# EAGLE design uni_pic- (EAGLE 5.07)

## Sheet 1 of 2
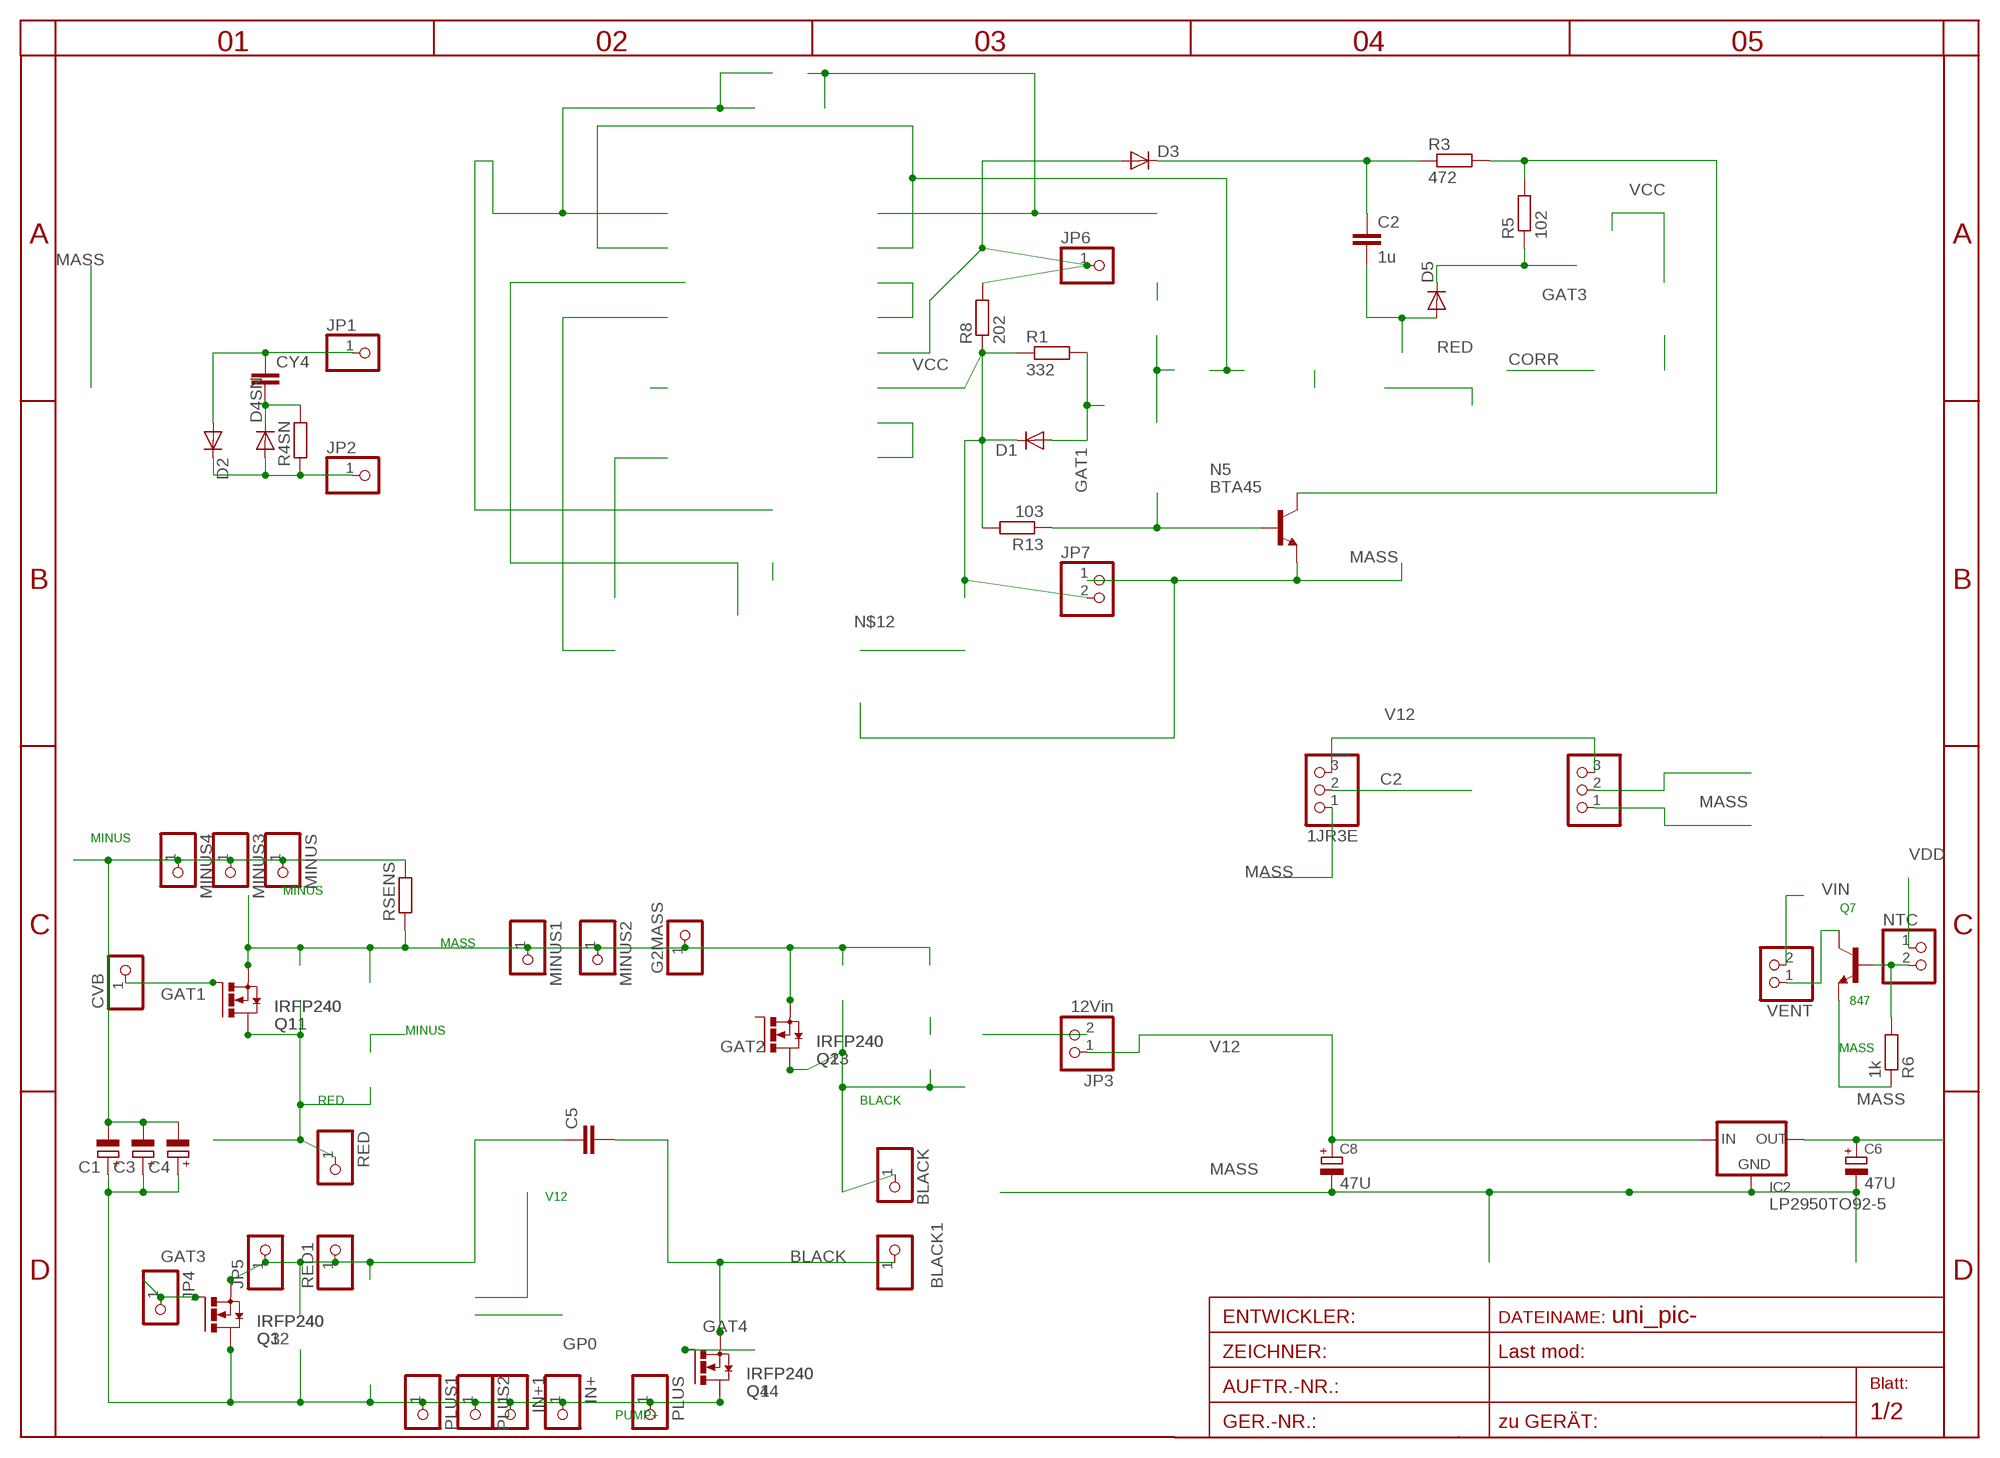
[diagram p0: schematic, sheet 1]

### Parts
1JR3E  PINHD-1X3  [1X03]
2JR4E3  PINHD-1X3  [1X03]
BLACK  PINHD-1X12MM3  [1X2MM3]
BLACK1  PINHD-1X12MM3  [1X2MM3]
C1  CPOL-EUE5-13  [E5-13]
C2  1u  C-EUC1206  [C1206]
C3  CPOL-EUE5-13  [E5-13]
C4  CPOL-EUE5-13  [E5-13]
C5  C-EU075-032X103  [C075-032X103]
C6  47U  CPOL-EUE5-6  [E5-6]
C8  47U  CPOL-EUE5-5  [E5-5]
CVB  PINHD-1X11MM0  [1X1MM0]
CY4  CXXC10B5  [XC10B5]
D1  DIODE-MINIMELF  [MINIMELF]
D2  DIODE-SMC  [SMC]
D3  DIODE-SMA-DO214  [SMA-DO214AC]
D4SN  DIODE-P1-10  [P1-10]
D5  DIODE-MINIMELF  [MINIMELF]
G2MASS  PINHD-1X11MM0  [1X1MM0]
IC2  LP2950TO92-5  [T092-5]
IN+  PINHD-1X12MM3  [1X2MM3]
IN+1  PINHD-1X12MM3  [1X2MM3]
JP1  PINHD-1X11MM0  [1X1MM0]
JP2  PINHD-1X11MM0  [1X1MM0]
JP3  12Vin  PINHD-1X2STR  [1X02]
JP4  PINHD-1X11MM0  [1X1MM0]
JP5  PINHD-1X11MM0  [1X1MM0]
JP6  PINHD-1X11X0.4  [1X01]
JP7  PINHD-1X2STR  [1X02]
MINUS  PINHD-1X12MM3  [1X2MM3]
MINUS1  PINHD-1X12MM3  [1X2MM3]
MINUS2  PINHD-1X12MM3  [1X2MM3]
MINUS3  PINHD-1X12MM3  [1X2MM3]
MINUS4  PINHD-1X12MM3  [1X2MM3]
N5  BTA45  SMBTA45HV  [SOT23HV]
NTC  PINHD-1X2STR  [1X02]
PLUS  PINHD-1X12MM3  [1X2MM3]
PLUS1  PINHD-1X12MM3  [1X2MM3]
PLUS2  PINHD-1X12MM3  [1X2MM3]
Q1  IRFP240  [TO247BV]
Q2  IRFP240  [TO247BV]
Q3  IRFP240  [TO247BV]
Q4  IRFP240  [TO247BV]
Q7  847  BC847ALT1SMD  [SOT23]
Q11  IRFP240  [TO247BV]
Q12  IRFP240  [TO247BV]
Q13  IRFP240  [TO247BV]
Q14  IRFP240  [TO247BV]
R1  332  R-EU_R0805  [R0805]
R3  472  R-EU_R0805  [R0805]
R4SN  R-EU_0207/10  [0207/10]
R5  102  R-EU_R1206  [R1206]
R6  1k  R-EU_R0805  [R0805]
R8  202  R-EU_R0805  [R0805]
R13  103  R-EU_0207/15  [0207/15]
RED  PINHD-1X12MM3  [1X2MM3]
RED1  PINHD-1X12MM3  [1X2MM3]
RSENS  R-EU_0204/7  [0204/7]
VENT  PINHD-1X2STR  [1X02]

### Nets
BLACK: BLACK1.1 BLACK.1 C5.2 Q2.D Q4.S Q13.D Q14.S
C1: 2JR4E3.2 ; also sheet 2
C2: 1JR3E.2 D1.C JP7.2 R1.1 R8.1 R13.2 ; also sheet 2
DRAIN: D2.C D4SN.A JP2.1 R4SN.1
GAT1: CVB.1 D1.A Q1.G Q11.G R1.2
GAT2: Q2.G Q13.G
GAT3: D5.C JP4.1 Q3.G Q12.G R5.1
GAT4: Q4.G Q14.G
MASS: 1JR3E.1 2JR4E3.1 C6.- C8.- G2MASS.1 IC2.2(GND) JP3.2 JP7.1 MINUS1.1 MINUS2.1 N5.2(E) Q1.S Q2.S Q7.2(E) Q11.S Q13.S R6.1 RSENS.1 ; also sheet 2
MINUS: C1.- C3.- C4.- MINUS3.1 MINUS4.1 MINUS.1 RSENS.2
N$4: C2.1 D3.K(C) R3.1
N$8: N5.3(C) R3.2 R5.2
N$9: NTC.2 Q7.1(B) R6.2
N$10: Q7.3(C) VENT.1
N$17: N5.1(B) R13.1
PUMP+: C1.+ C3.+ C4.+ IN+1.1 IN+.1 PLUS1.1 PLUS2.1 PLUS.1 Q3.D Q4.D Q12.D Q14.D ; also sheet 2
RED: C2.2 C5.1 D5.A JP5.1 Q1.D Q3.S Q11.D Q12.S RED1.1 RED.1
SNUB2: CY4.2 D4SN.C R4SN.2
SOURCE: CY4.1 D2.A JP1.1
V12: 1JR3E.3 2JR4E3.3 C8.+ IC2.3(IN) JP3.1
VCC: D3.A JP6.1 R8.2
VDD: C6.+ IC2.1(OUT) NTC.1 ; also sheet 2
VIN: VENT.2

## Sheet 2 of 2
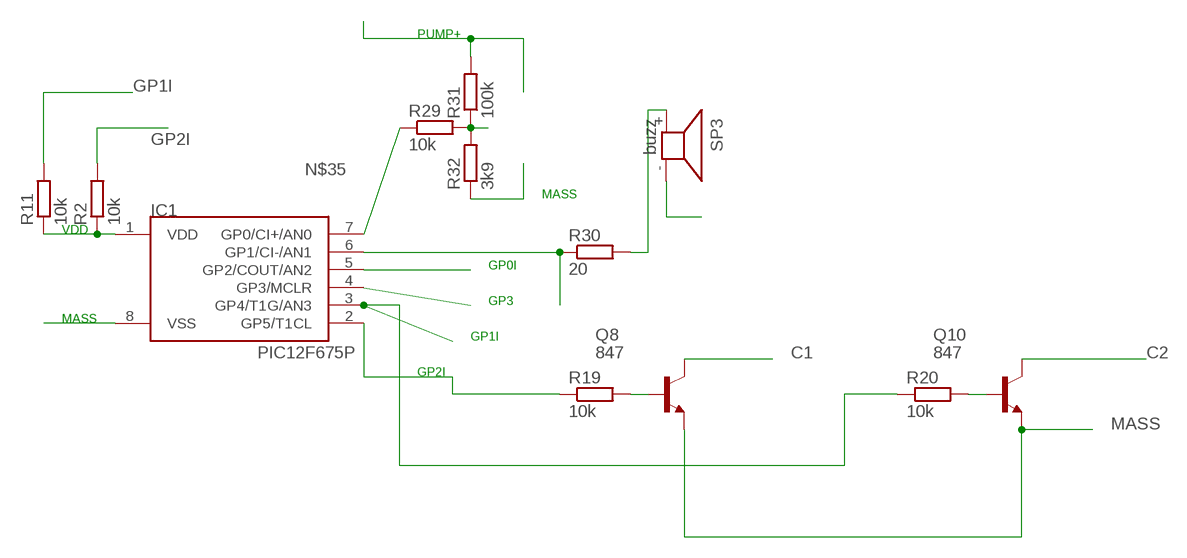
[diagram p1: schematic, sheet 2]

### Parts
IC1  PIC12F675P  [DIL8]
Q8  847  BC847ALT1SMD  [SOT23]
Q10  847  BC847ALT1SMD  [SOT23]
R2  10k  R-EU_R0805  [R0805]
R11  10k  R-EU_R0805  [R0805]
R19  10k  R-EU_R0805  [R0805]
R20  10k  R-EU_R0805  [R0805]
R29  10k  R-EU_R0805  [R0805]
R30  20  R-EU_R0805  [R0805]
R31  100k  R-EU_0207/20  [0207/20]
R32  3k9  R-EU_R0805  [R0805]
SP3  buzz  KSS12017MM  [KSS1202]

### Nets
C1: Q8.3(C) ; also sheet 1
C2: Q10.3(C) ; also sheet 1
GP0I: IC1.5(GP2/COUT/AN2)
GP1I: IC1.3(GP4/T1G/AN3) R11.2 R20.1
GP2I: IC1.2(GP5/T1CL) R2.2 R19.1
GP3: IC1.4(GP3/MCLR)
MASS: IC1.8(VSS) Q8.2(E) Q10.2(E) R32.1 SP3.- ; also sheet 1
N$22: Q10.1(B) R20.2
N$24: R30.2 SP3.+
N$28: Q8.1(B) R19.2
N$31: IC1.6(GP1/CI-/AN1) R30.1
N$34: R29.2 R31.1 R32.2
N$35: IC1.7(GP0/CI+/AN0) R29.1
PUMP+: R31.2 ; also sheet 1
VDD: IC1.1(VDD) R2.1 R11.1 ; also sheet 1

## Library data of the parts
1JR3E 2JR4E3 = pinhead:PINHD-1X3: PIN HEADER
BLACK BLACK1 CVB G2MASS IN+ IN+1 JP1 JP2 JP4-JP6 MINUS MINUS1-MINUS4 PLUS PLUS1 PLUS2 RED RED1 = pinhead:PINHD-1X1: PIN HEADER
C1 C3 C4 = rcl:CPOL-EU: POLARIZED CAPACITOR, European symbol
C2 C5 = rcl:C-EU: CAPACITOR, European symbol
C6 C8 = rcl-2:CPOL-EU: POLARIZED CAPACITOR, European symbol
CY4 = rcl:CX: X CAPACITOR
D1-D3 D4SN D5 = diode:DIODE-: DIODE
IC1 = microchip-5:PIC12F6*: uPC nW 1k Program Flash memory 2x Timer Comparator 10b A/D converter/ 4xIN
IC2 = v-reg:LP2950?*: Source: http://cache.national.com/ds/LP/LP2950.pdf
JP3 JP7 NTC VENT = pinhead:PINHD-1X2: PIN HEADER
N5 = transistor-npn:SMBTA45
Q1-Q4 Q11-Q14 = transistor-power:IRFP240: HEXFET Power MosFet Source: http://www.irf.com/
Q7 Q8 Q10 = transistor-npn:BC847*: NPN Transistor
R1 R3 R4SN R5 R6 R8 R13 RSENS = rcl:R-EU_: RESISTOR, European symbol
R2 R11 R19 R20 R29-R32 = rcl-2:R-EU_: RESISTOR, European symbol
SP3 = buzzer:KSS1201: SPEAKER

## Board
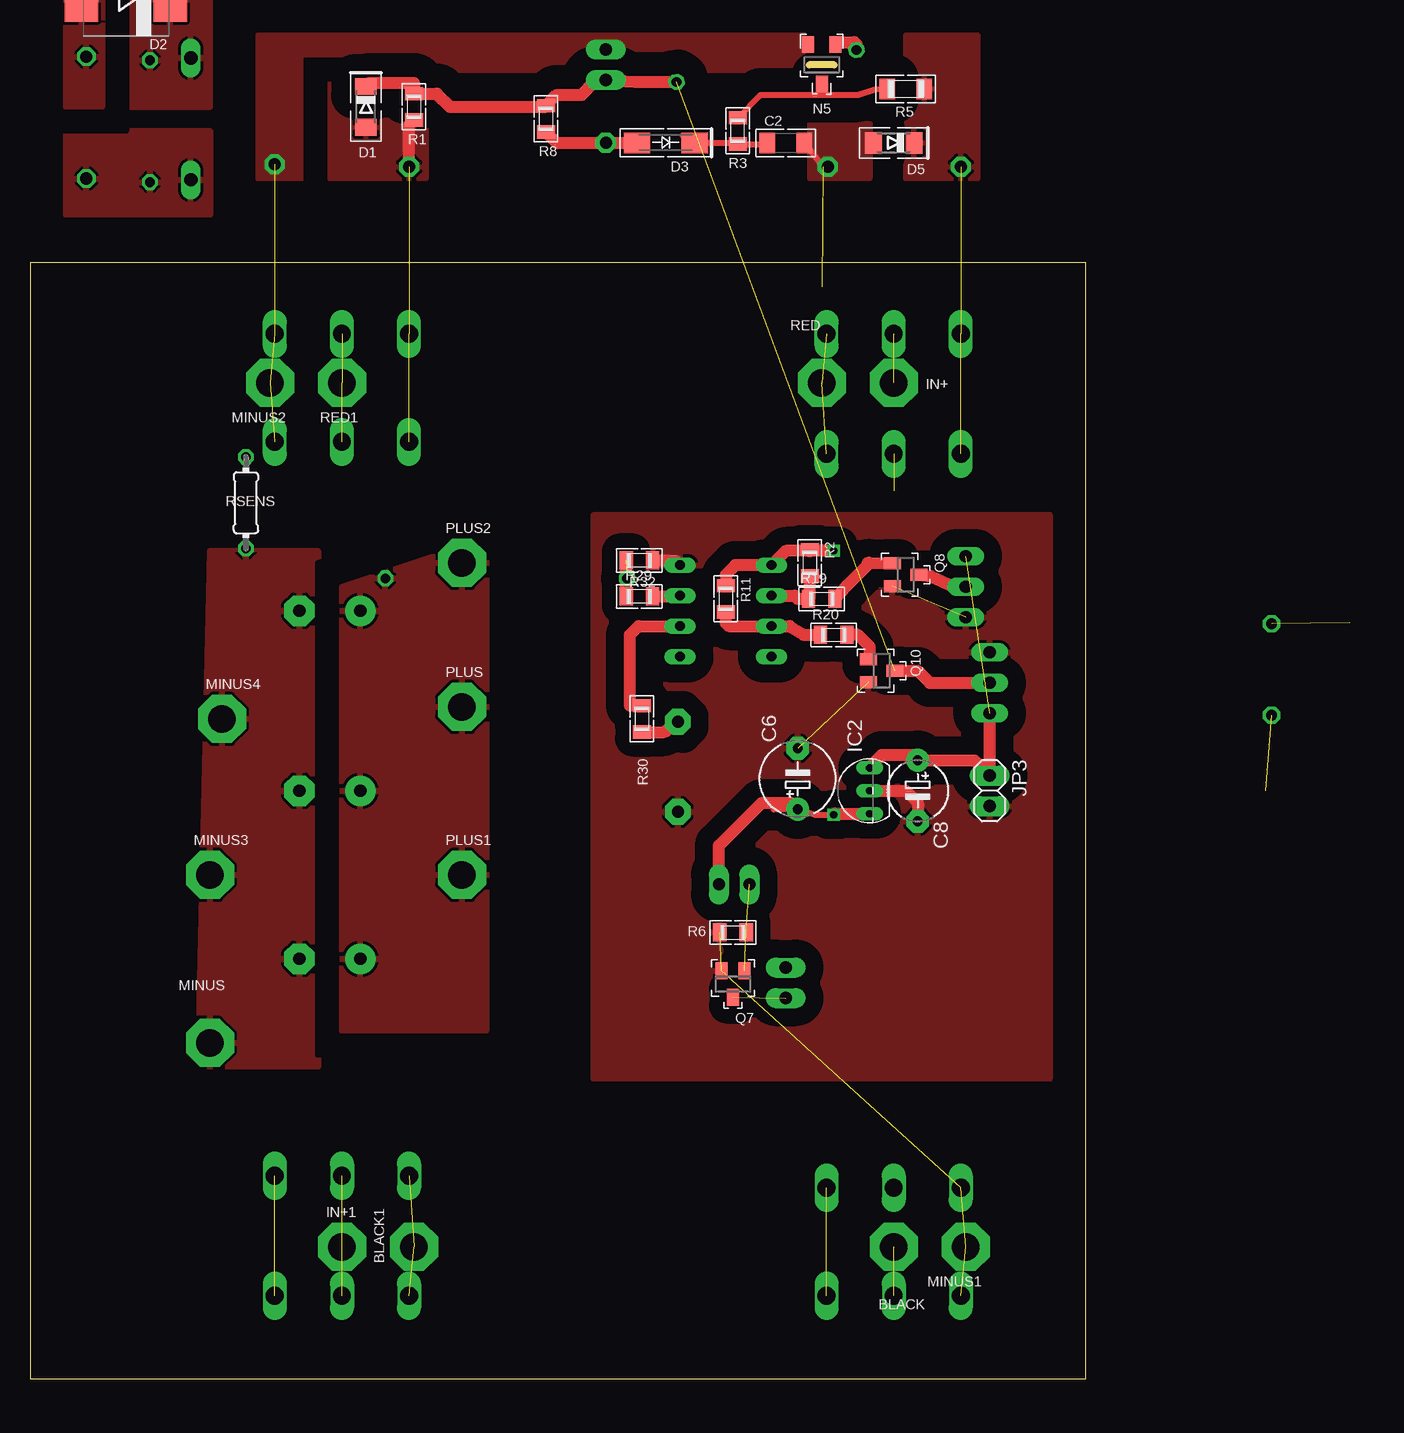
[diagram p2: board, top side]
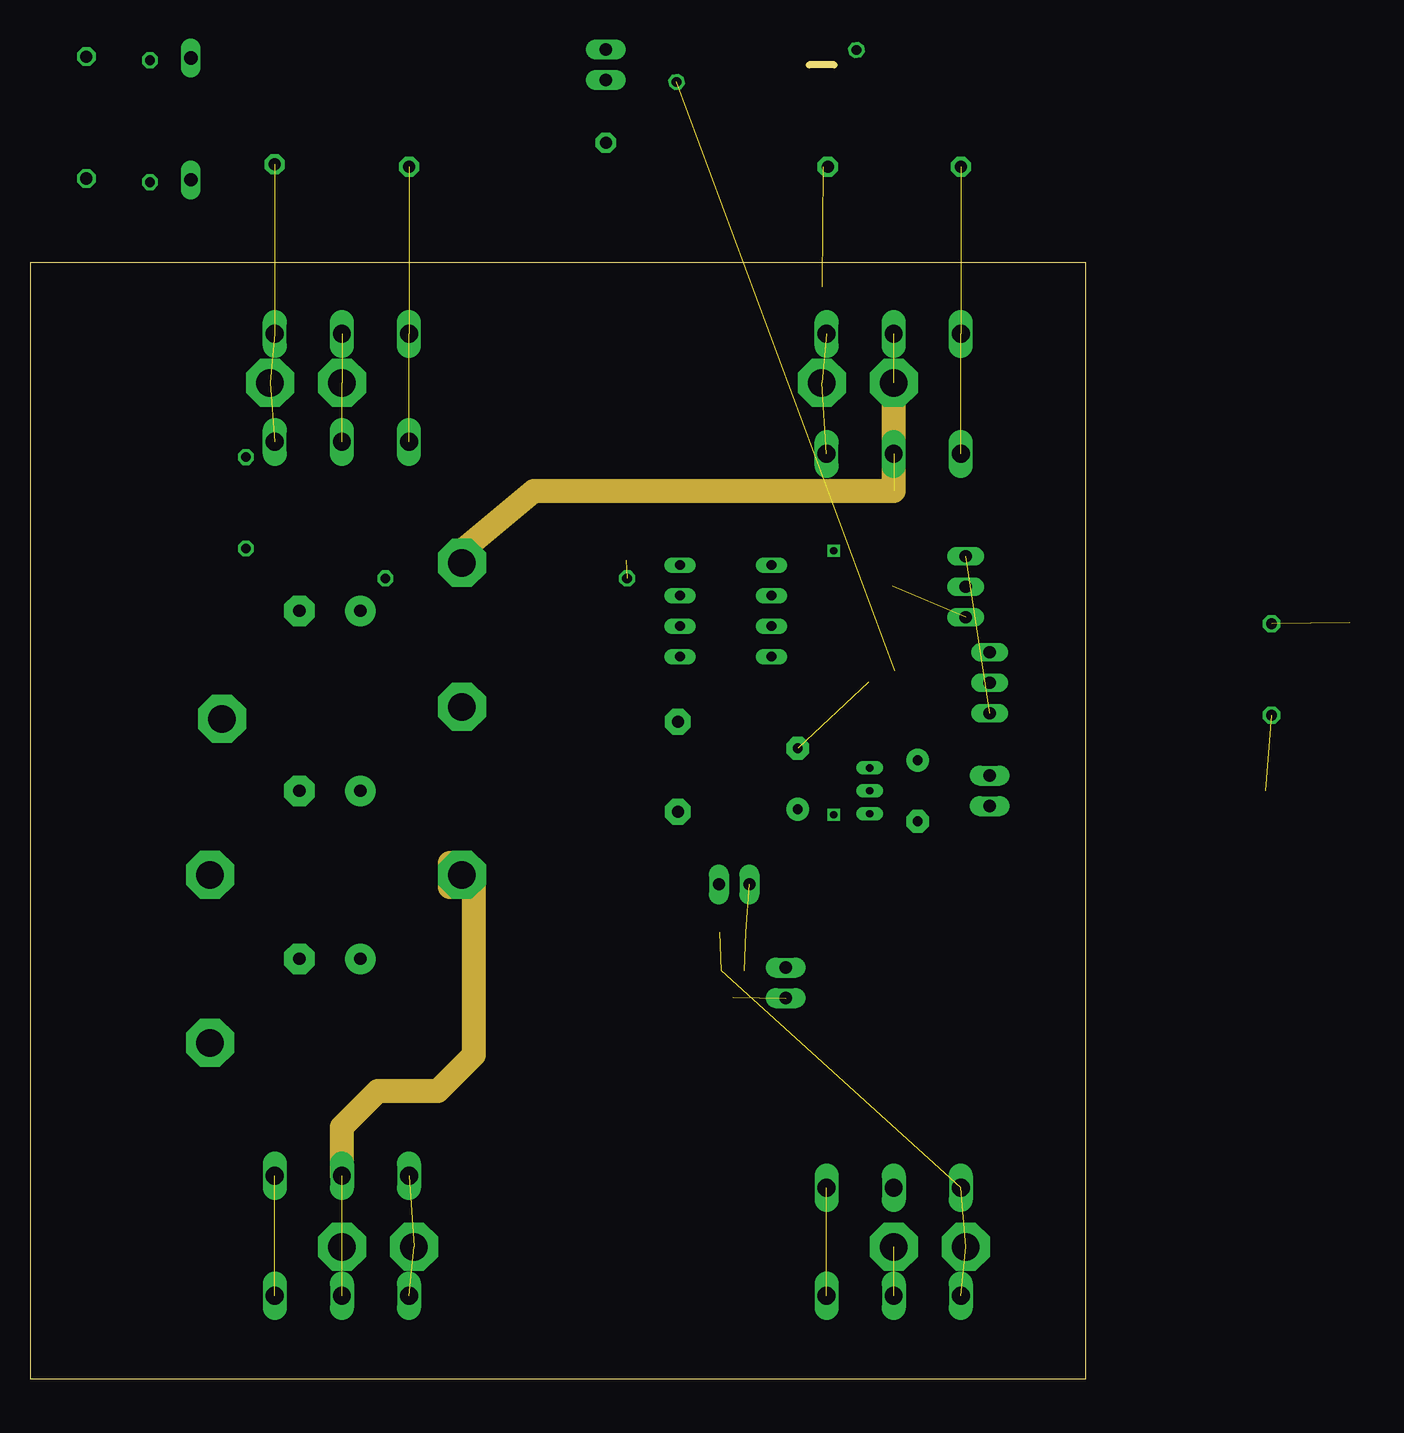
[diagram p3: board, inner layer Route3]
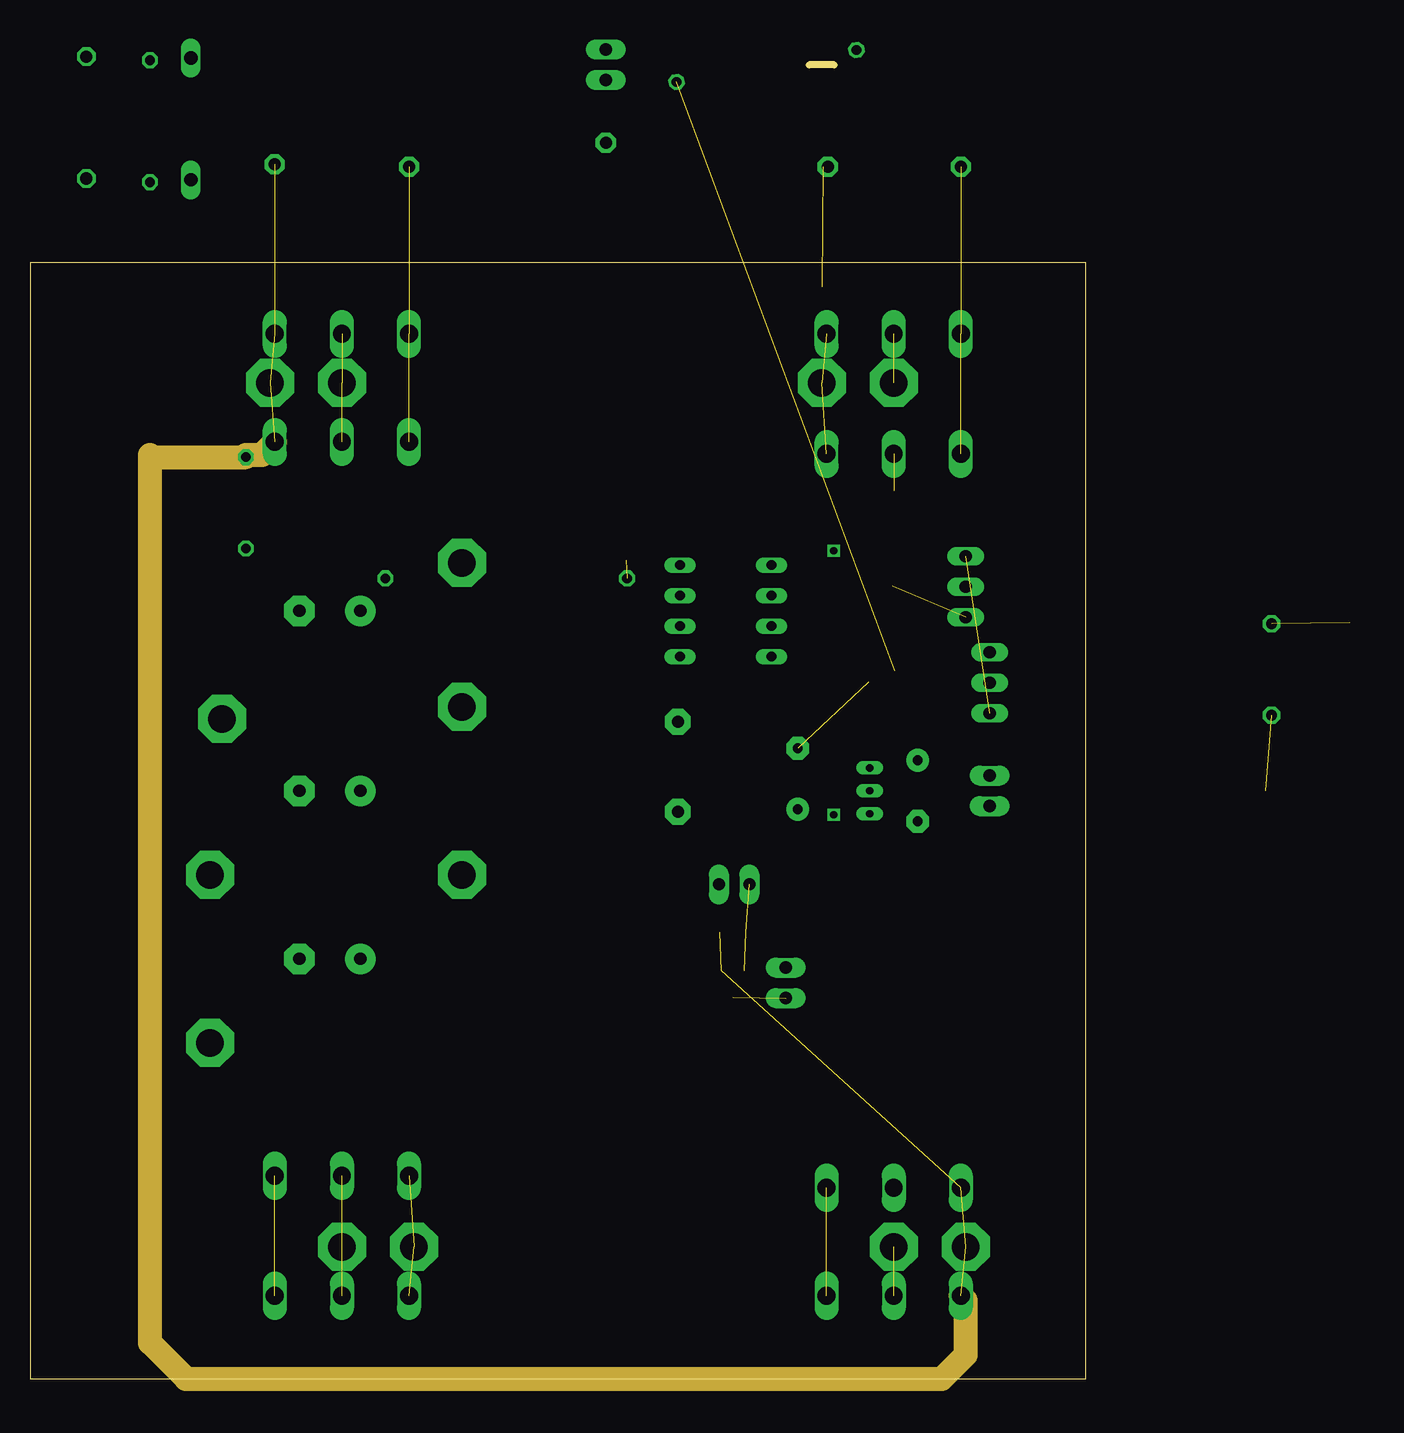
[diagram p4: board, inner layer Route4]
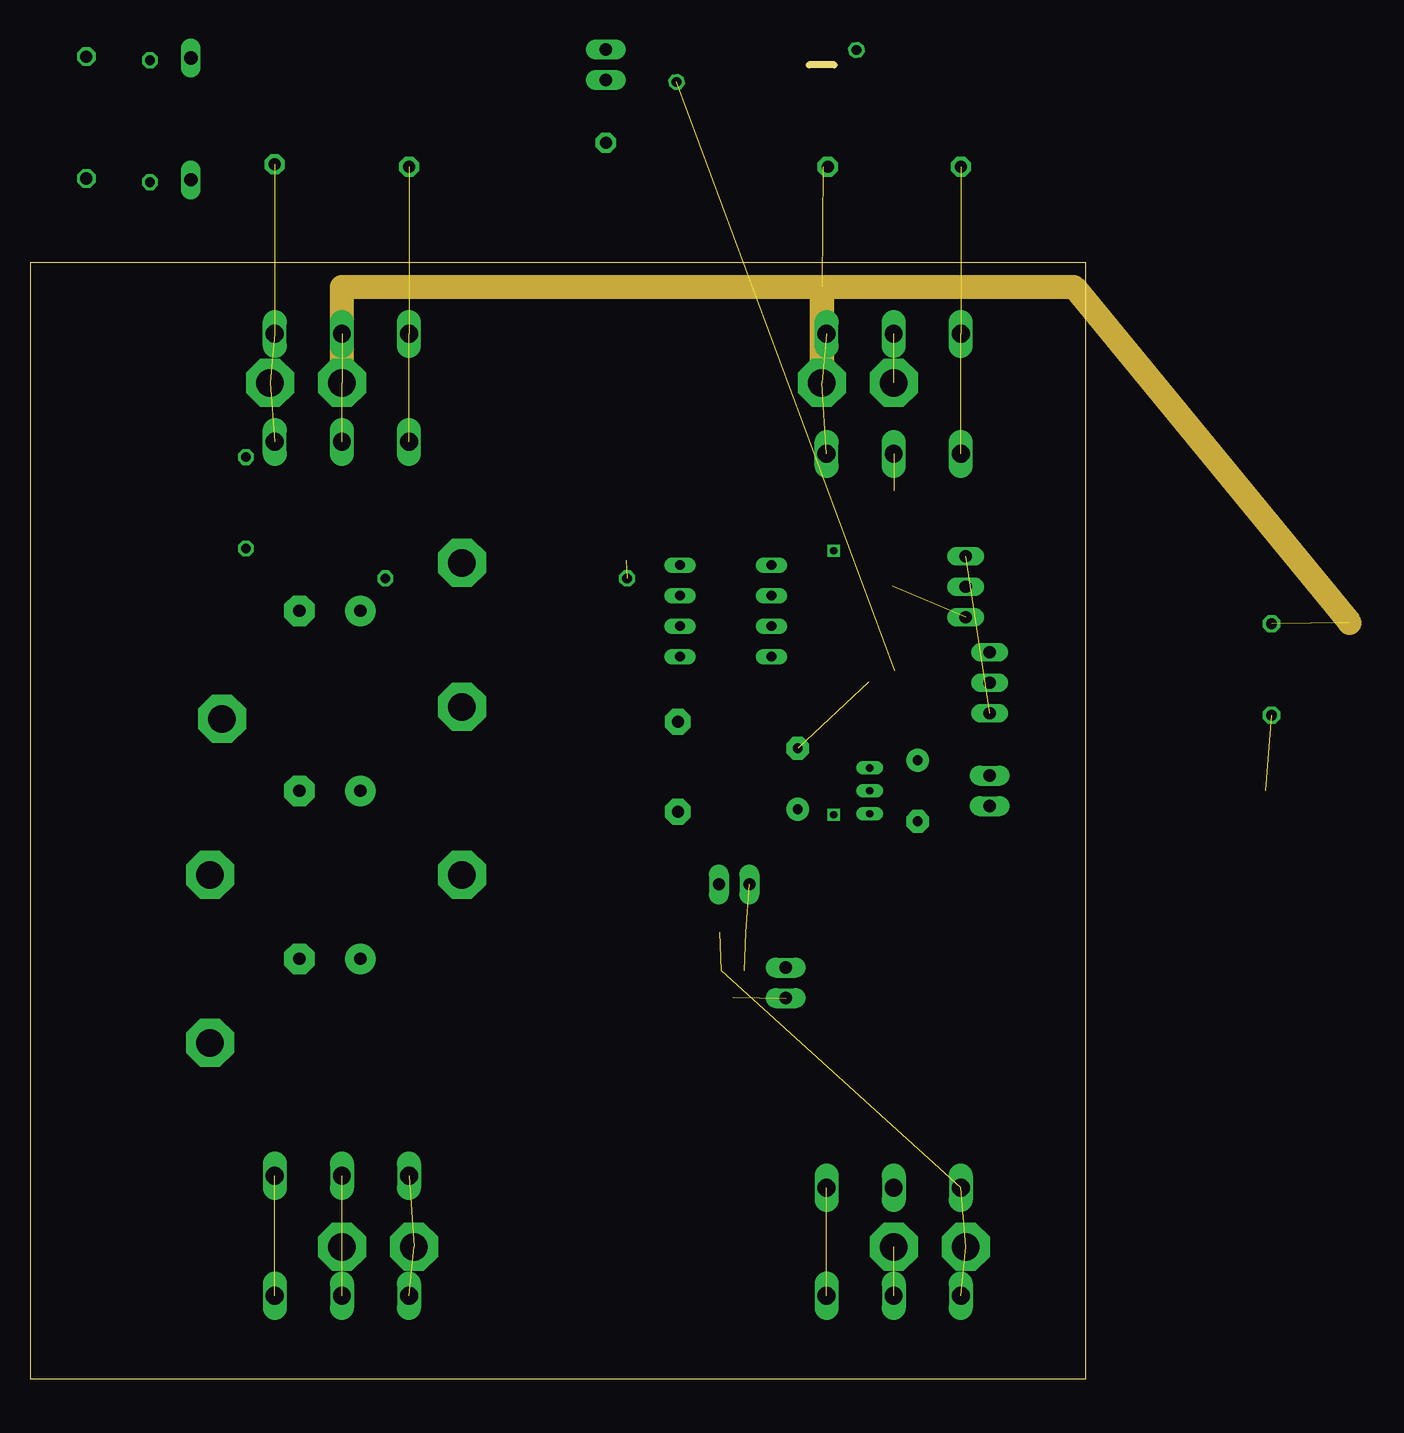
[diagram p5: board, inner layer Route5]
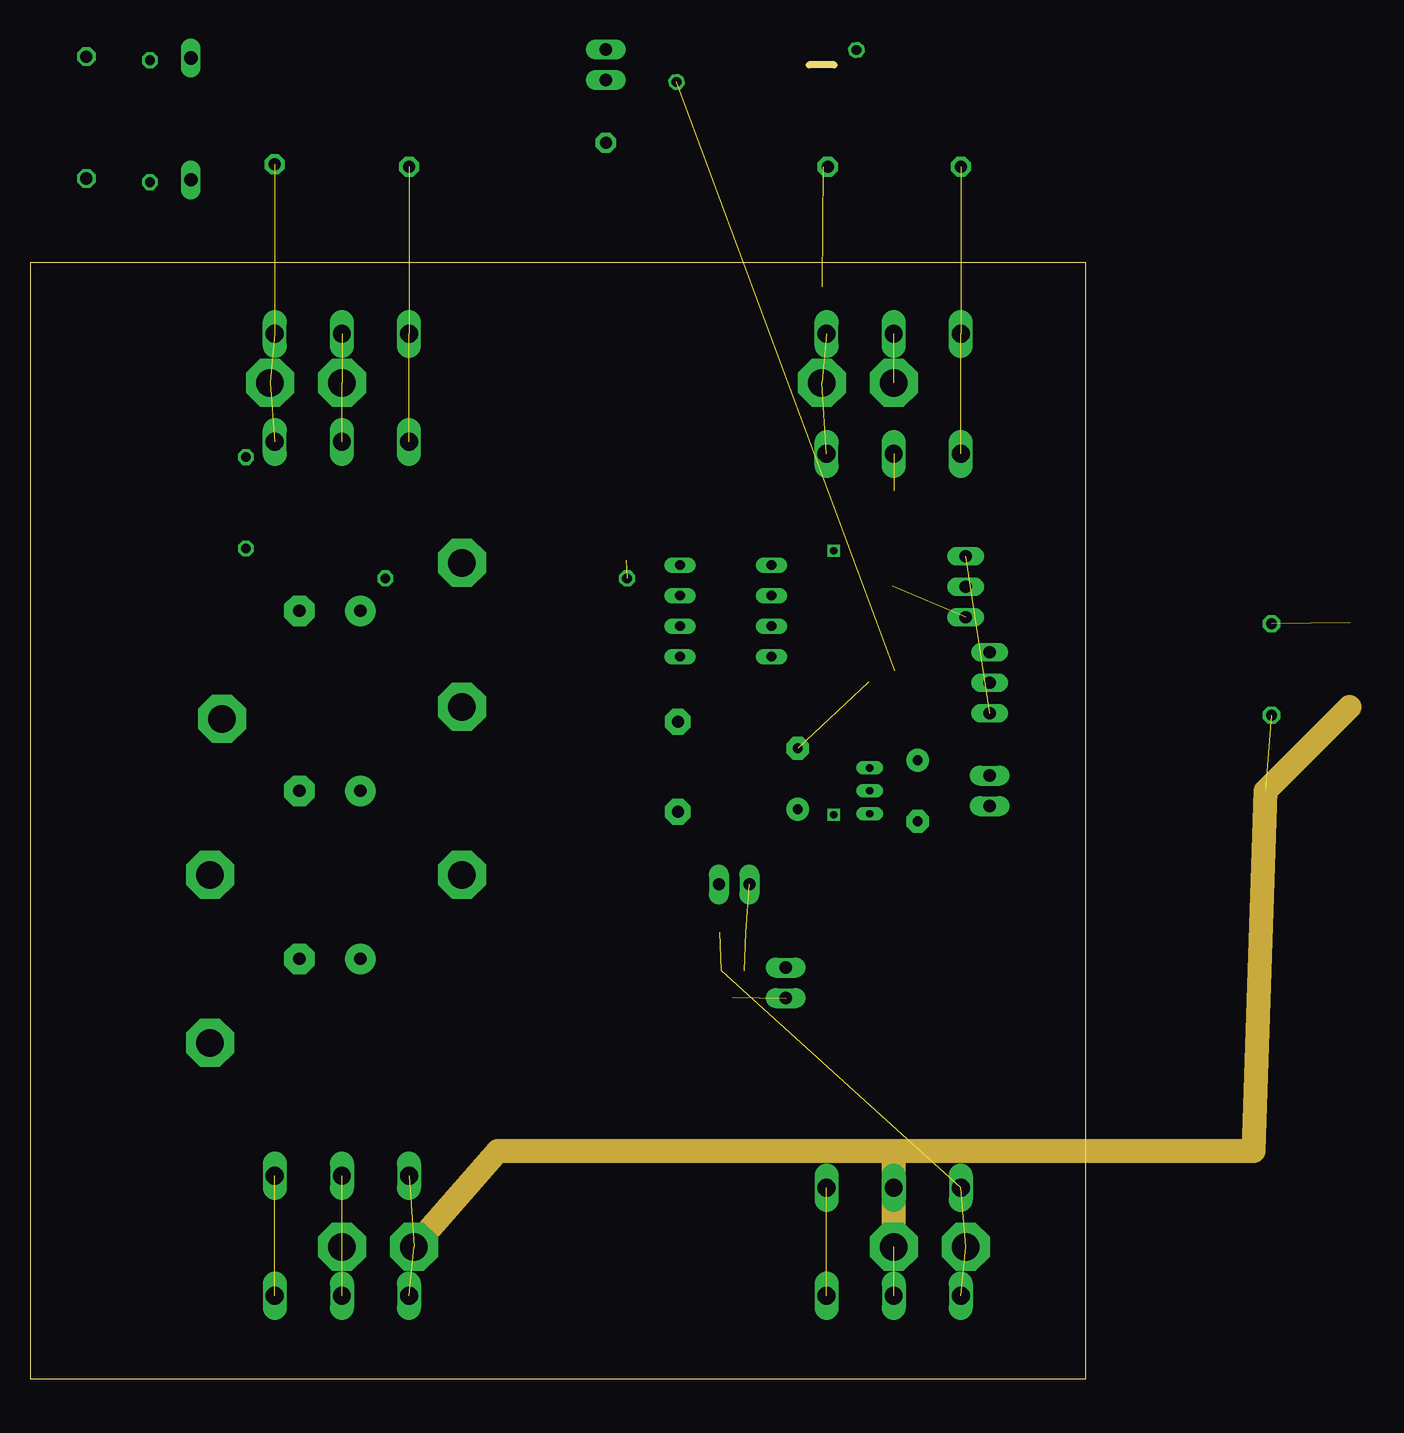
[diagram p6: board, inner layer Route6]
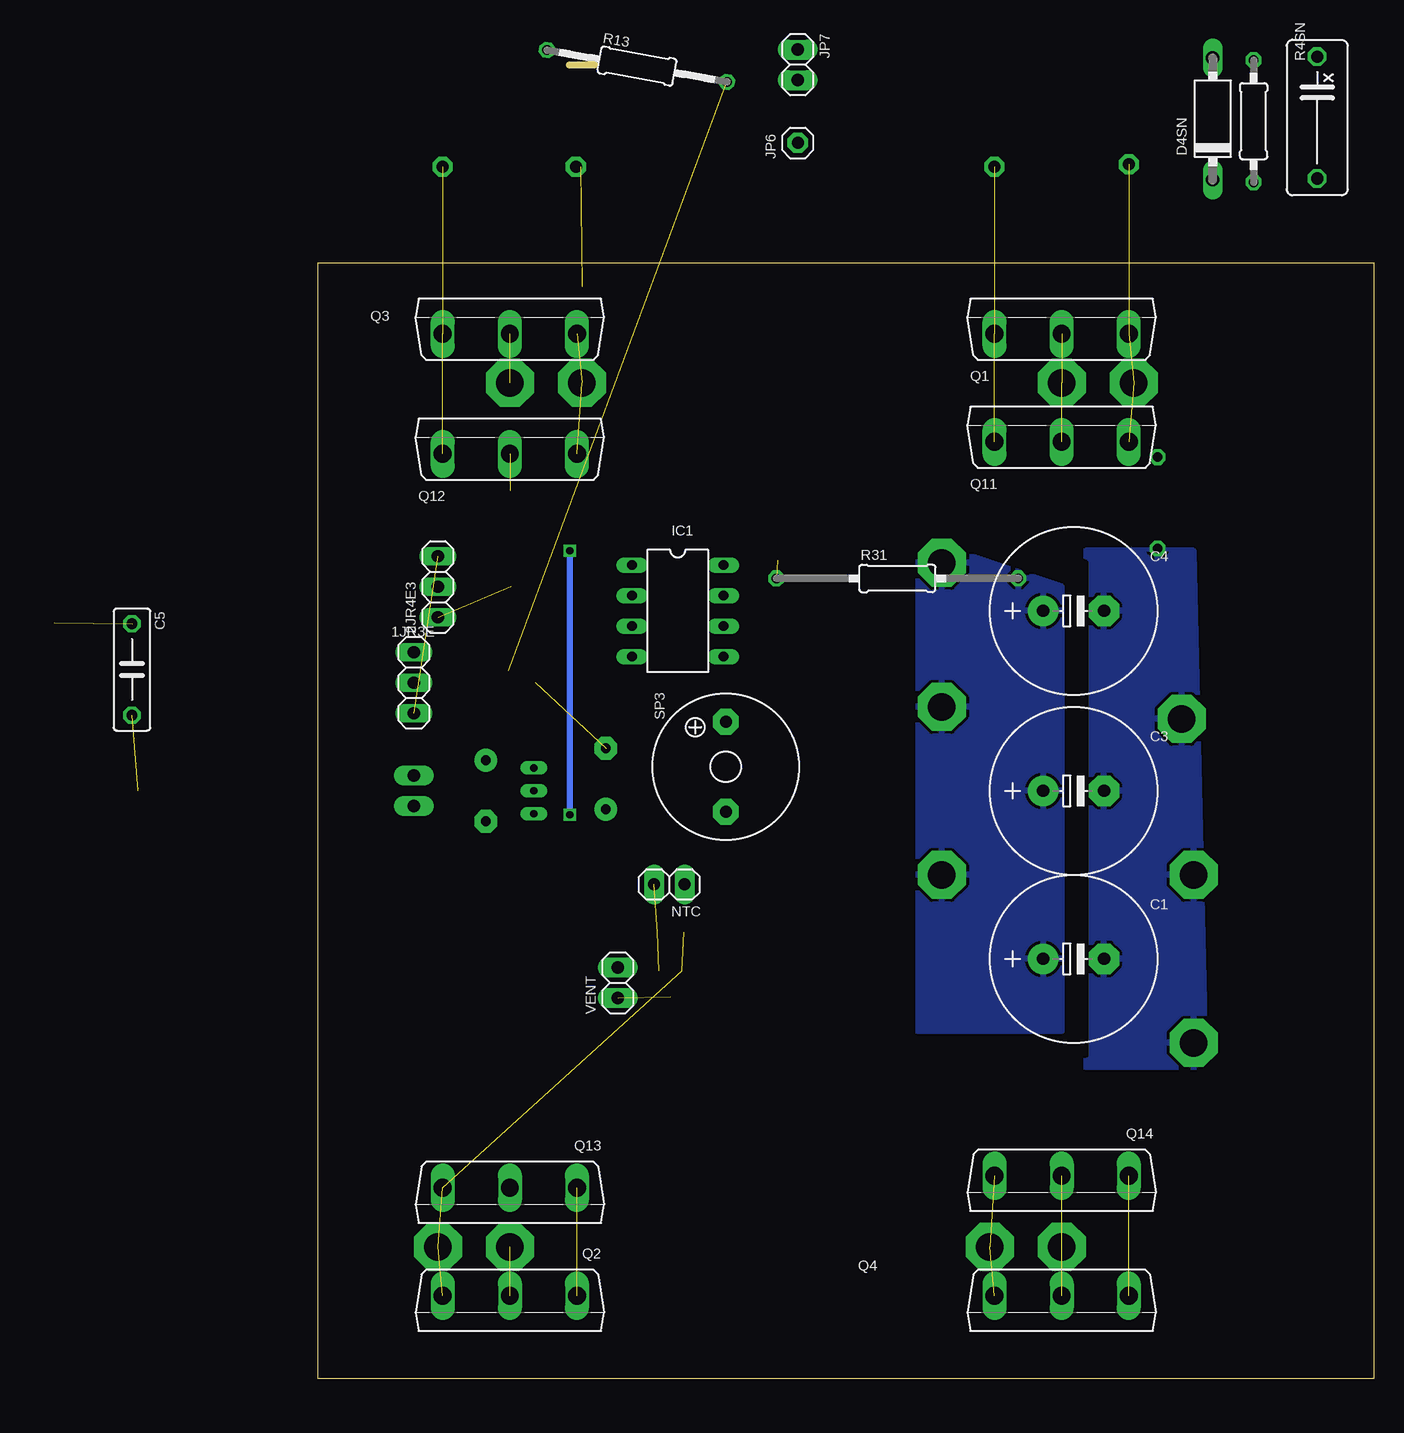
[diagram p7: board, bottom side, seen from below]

Size 88 x 93 mm. Coordinates in mm from the lower left corner, seen from the top.
Outline: 0,0 88,0 88,93 0,93 0,0
Copper layers (1*16): Top 0.035mm / dielectric 1.5mm / Bottom 0.035mm
Design rules "default *": minimum track width 10mil, minimum drill 20mil, track to track 8mil, track to pad 8mil, pad to pad 8mil, via to via 8mil, smd to smd 8mil, copper to edge 40mil, drill to drill 8mil, minimum pad ring 10mil, minimum via ring 8mil, stop-mask expansion 4mil, vias tented up to drill 0mil, thermal gap 10mil

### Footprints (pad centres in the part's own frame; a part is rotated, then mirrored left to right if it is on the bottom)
1X03 = drill 1.016 long: 1 -2.54,0; 2 0,0; 3 2.54,0
1X2MM3 = drill 2.3 pad 4 octagon: 1 0,0
E5-13 = drill 1.016 pad 2.54 round: + -2.54,0 | drill 1.016 pad 2.54 octagon: - 2.54,0
C1206 = smd 1.3 x 1.7: 1 -1.55,0; 2 1.55,0
C075-032X103 = drill 0.914 octagon: 1 -3.81,0; 2 3.81,0
E5-6 = drill 0.813 pad 1.905 round: + -2.54,0 | drill 0.813 pad 1.905 octagon: - 2.54,0
E5-5 = drill 0.813 pad 1.905 round: + -2.54,0 | drill 0.813 pad 1.905 octagon: - 2.54,0
1X1MM0 = drill 1 pad 1.676 octagon: 1 0,0
XC10B5 = drill 1.016 octagon: 1 -5.08,0; 2 5.08,0
MINIMELF = smd 1.4 x 1.8: A 1.7,0; C -1.7,0
SMC = smd 2.8 x 3.8: A 3.7,0; C -3.7,0
SMA-DO214AC = smd 2.2 x 1.7: A 2.4,0; K -2.4,0
P1-10 = drill 1.118 long: A 5.08,0; C -5.08,0
DIL8 = drill 0.8 long: 1 -3.81,-3.81; 2 -1.27,-3.81; 3 1.27,-3.81; 4 3.81,-3.81; 5 3.81,3.81; 6 1.27,3.81; 7 -1.27,3.81; 8 -3.81,3.81
T092-5 = drill 0.6 pad 0.813 long: 1 -1.905,0; 2 0,0; 3 1.905,0
1X02 = drill 1.016 pad 1.676 long: 1 -1.27,0; 2 1.27,0
1X01 = drill 1 pad 1.676 octagon: 1 0,0
SOT23HV = smd 1 x 1.4: 1 -1.15,-1.7; 2 1.15,-1.7; 3 0,1.6
TO247BV = drill 1.499 long: D 0,-2.921; G -5.588,-2.921; S 5.588,-2.921
SOT23 = smd 1 x 1.4: 1 -0.95,-1.1; 2 0.95,-1.1; 3 0,1.1
R0805 = smd 1.1 x 1.5: 1 -1.1,0; 2 1.1,0
0207/10 = drill 0.813 octagon: 1 -5.08,0; 2 5.08,0
R1206 = smd 1.3 x 1.7: 1 -1.55,0; 2 1.55,0
0207/15 = drill 0.813 octagon: 1 -7.62,0; 2 7.62,0
0207/20 = drill 0.813 octagon: 1 -10.08,0; 2 10.08,0
0204/7 = drill 0.813 octagon: 1 -3.81,0; 2 3.81,0
KSS1202 = drill 1 pad 2.159 octagon: + 3.75,0; - -3.75,0

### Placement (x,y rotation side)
1JR3E  80,58 270 bottom
2JR4E3  78,66 90 bottom
BLACK  72,11 180 top
BLACK1  32,11 90 top
C1  25,35 0 bottom
C2  63,103 0 top  (outside the outline)
C3  25,49 0 bottom
C4  25,64 0 bottom
C5  not placed on the board
C6  64,50 90 top
C8  74,49 270 top
CVB  31.6,101 0 top  (outside the outline)
CY4  not placed on the board
D1  28,106 270 top  (outside the outline)
D2  not placed on the board
D3  53,103 180 top  (outside the outline)
D4SN  not placed on the board
D5  not placed on the board
G2MASS  not placed on the board
IC1  58,64 270 bottom
IC2  70,49 90 top
IN+  72,83 0 top
IN+1  26,11 0 top
JP1  not placed on the board
JP2  not placed on the board
JP3  80,49 270 top
JP4  not placed on the board
JP5  66.5,101 180 top  (outside the outline)
JP6  48,103 90 bottom  (outside the outline)
JP7  48,109.5 270 bottom  (outside the outline)
MINUS  15,28 0 top
MINUS1  78,11 180 top
MINUS2  20,83 180 top
MINUS3  15,42 0 top
MINUS4  16,55 0 top
N5  66,109.5 180 top  (outside the outline)
NTC  58.7,41.2 180 bottom
PLUS  36,56 0 top
PLUS1  36,42 0 top
PLUS2  36,68 0 top
Q1  26,90 0 bottom
Q2  72,4 180 bottom
Q3  72,90 0 bottom
Q4  26,4 180 bottom
Q7  58.6,32.9 180 top
Q8  73,67 270 top
Q10  71,59 270 top
Q11  26,81 0 bottom
Q12  72,80 0 bottom
Q13  72,13 180 bottom
Q14  26,14 180 bottom
R1  32,106 270 top  (outside the outline)
R2  65,68 270 top
R3  59,104 90 top  (outside the outline)
R4SN  not placed on the board
R5  73,107.5 180 top  (outside the outline)
R6  58.6,37.2 0 top
R8  43,105 270 top  (outside the outline)
R11  58,65 270 top
R13  61.4,109.4 350 bottom  (outside the outline)
R19  66,65 0 top
R20  67,62 0 top
R29  50.8,65.2 180 top
R30  51,55 270 top
R31  39.7,66.7 0 bottom
R32  50.8,68.2 180 top
RED  66,83 0 top
RED1  26,83 180 top
RSENS  18,73 270 top
SP3  54,51 90 bottom
VENT  63,33 90 bottom

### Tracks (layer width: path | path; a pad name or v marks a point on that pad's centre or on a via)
BLACK  (4 unrouted)
  Route6 2: BLACK1.1 39,19 72,19 | 72,19 BLACK.1 Q13.D | 72,19 102,19 103,49 110,56
C1
  Top 1: Q8.3 75.1,66.9 77,66 2JR4E3.2
C2  (1 unrouted)
  Top 1: R13.2 50.45,108.08 JP7.2 47.03,108.03 46,107 43.9,107 R8.1 42.9,106 35,106 33.9,107.1 R1.1 32,108 28.3,108 D1.C | Q10.3 74,59 75,58 1JR3E.2
DRAIN
  pour Top (isolate 2, rank 2): 8,120 8,106 15,106 15,120
GAT1  (2 unrouted)
  Top 1: R1.2 31.6,104.5 CVB.1
  pour Top (isolate 2): 25,100 25,108 33,108 33,100
GAT2  (1 unrouted)
GAT3  (2 unrouted)
  pour Top (isolate 2, rank 2): 73,112 79,112 79,100 73,100
GAT4  (1 unrouted)
GP1I
  Top 1: R20.1 64.5,62 63.33,62.73 IC1.3 58.27,62.73 58,63 R11.2
GP2I
  Top 1: IC1.2 63.73,65.27 64,65 R19.1 65,65.1 R2.2
MASS  (9 unrouted)
  Top 1: C8.- 74,48 73,49 IC2.2 | R32.1 53.8,68.2 IC1.8
  Route4 2: Q11.S 19.33,77 18,77 RSENS.1 10.19,76.81 10,77 10,3 13,0 76,0 78,2 78,6.51 Q2.S
  pour Top (isolate 1.5): 47,72 85,72 85,25 47,25
  pour Top (isolate 2, rank 2, no thermals): 19,112 65,112 65,109 23,109 23,100 19,100
MINUS
  pour Top (isolate 2, rank 2): 15,69 24,69 24,26 14,26
  pour Bottom (isolate 2, rank 2): 15,69 24,69 24,26 14,26
N$4
  Top 0.5: C2.1 61.8,102.9 R3.1 58.9,103 55,103 54.4,103.6 D3.K
N$8
  Top 0.5: R5.2 70.45,107.45 69,107 66,107 | R3.2 60.9,107 66,107 | 66,107 N5.3
N$9  (2 unrouted)
N$10  (1 unrouted)
N$17
  Top 1: N5.1 67.35,111.4 68.7,111.4 68.9,111.2 R13.1
N$22
  Top 1: R20.2 69,62 70,61 70,60.05 Q10.1
N$24
  Top 1: R30.2 52.85,53.9 SP3.+
N$28
  Top 1: R19.2 68.1,66.1 70,68 69.85,68 Q8.1
N$31
  Top 1: IC1.6 50.73,62.73 50,62 50,56.1 R30.1
N$34  (1 unrouted)
  Top 1: R29.2 R32.2
N$35
  Top 1: R29.1 54.12,65.2 IC1.7
PUMP+  (4 unrouted)
  Route3 2: PLUS2.1 36,69 42,74 72,74 IN+.1 | Q14.D 26,21 29,24 34,24 37,27 37,41 PLUS1.1 | PLUS1.1 35,43 35,42 | 35,42 35,41 | PLUS1.1 35,42
  pour Top (isolate 2): 26,66 38,70 38,29 26,29
  pour Bottom (isolate 2): 26,66 38,70 38,29 26,29
RED  (6 unrouted)
  Top 0.5: C2.2 66.1,101 JP5.1 67,101
  Route5 2: RED1.1 26,91 66,91 | 66,91 RED.1 66,91 | 66,91 87,91 110,63
  pour Top (isolate 2, no thermals): 65,105 70,105 70,100 65,100
SNUB2
  pour Top (isolate 2, rank 2): 3,104 15,104 15,97 3,97
SOURCE
  pour Top (isolate 2): 3,120 6,120 6,106 3,106
V12  (1 unrouted)
  Top 1: 1JR3E.3 JP3.1 78.73,51.54 C8.+ 73.54,52 71,52 70,51 IC2.3
VCC
  Top 1: D3.A JP6.1 43.9,103 R8.2
VDD  (via drill 0.6)
  Top 0.5: 62,48 62,47.46 C6.+ 65.46,47 v67,47 | IC1.1 61.19,67.81
  Top 1: R11.1 58,67 58.81,67.81 61.19,67.81 | IC1.1 63,69 64.9,69 R2.1 65.1,69 v67,69 | IC2.1 67.09,47.09 v67,47 | NTC.1 57.43,44.43 61,48 63.46,48 C6.+
  Bottom 0.5: v67,47 v67,69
